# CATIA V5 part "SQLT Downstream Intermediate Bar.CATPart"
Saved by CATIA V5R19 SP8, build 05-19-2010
Part number: SQLT Downstream Intermediate Bar 27
Publications: "Droite.1", "Plan.1", "Plan.2", "Droite.2", "Droite.3", "Plan.3", "Plan.4"
Bounding box of the stored display mesh (mm): x -150 to 150, y 1000 to 1100, z 450 to 500
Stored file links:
  G:\EU_thinkMotion\CFAO_2010\MMS_groupe3\MMS_groupe3\A reprendre\fovide\fovide\SQLT Downstream Intermediate Bar.CATPart
  G:\EU_thinkMotion\CFAO_2010\MMS_groupe3\MMS_groupe3\A reprendre\fovide\fovide\fovide.CATProduct
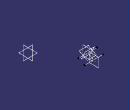
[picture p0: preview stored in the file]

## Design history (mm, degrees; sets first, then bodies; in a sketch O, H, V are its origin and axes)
Set1
  Point1 "Point.D": linked copy from another document
  Point2 "Point.E": linked copy from another document
Set2 "set Downstream Intermediate Bar"
  Line1: type PtPt, FirstPoint Point1, SecondPoint Point2
  Plane1: type OffsetPt, RefPlane yz-plane, RefPoint Point1
  Plane2: type OffsetPt, RefPlane yz-plane, RefPoint Point2
  Line2: type Normal, RefPoint Point1, RefSkin Plane1, Start -150, End 150
  Line3: type Normal, RefPoint Point2, RefSkin Plane2, Start -150, End 150
  Plane3: type Normal, Curve Line1, RefPoint Point1
  Plane4: type Angle, RefPlane Plane3, Direction Line2, Angle 90
Body1 (main body)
